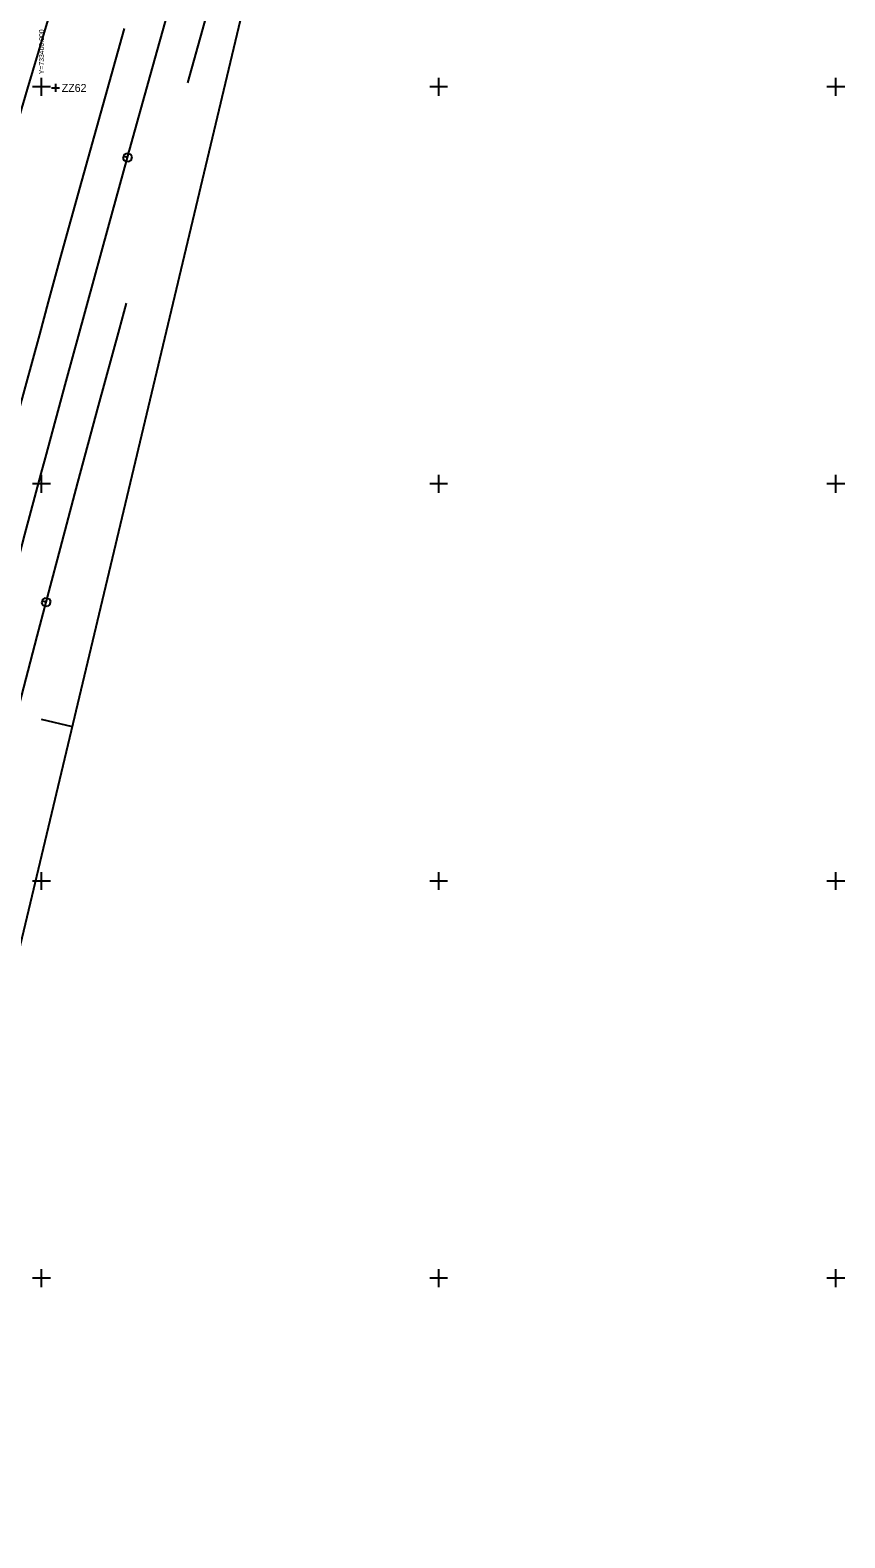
# Model space of a CAD drawing. Extents: x -733601 to -733291, y -1137892 to -1137187.
# Drawn here: x -733401.4 to -733298.9, y -1137682.7 to -1137492.9 of the extents above; entities that cross this region are included whole.
import ezdxf

# ---------------------------------------------------------------- set-up
doc = ezdxf.new("R2010")
doc.units = 0
for name, color, linetype in [('BP_ZBP_a_ZZ', 7, 'Continuous'), ('Krizky_Hektom_sit', 7, 'Continuous'), ('Rozvrzeni', 7, 'Continuous'), ('SIT_PUV_ZELEZNICE', 7, 'Continuous')]:
    doc.layers.add(name, color=color, linetype=linetype)

msp = doc.modelspace()

# ---------------------------------------------------------------- linework, layer by layer
at = {"layer": 'BP_ZBP_a_ZZ'}
for p, q in [((-733398.74, -1137500.13), (-733397.74, -1137500.13)), ((-733398.24, -1137499.63), (-733398.24, -1137500.63))]:
    msp.add_line(p, q, dxfattribs=at)
at = {"layer": 'Krizky_Hektom_sit'}
for p, q in [((-733400, -1137501.13), (-733400, -1137498.87)), ((-733350, -1137501.13), (-733350, -1137498.87)), ((-733300, -1137501.13), (-733300, -1137498.87)), ((-733398.87, -1137500), (-733401.13, -1137500)), ((-733348.87, -1137500), (-733351.13, -1137500)), ((-733298.87, -1137500), (-733301.13, -1137500)), ((-733398.87, -1137550), (-733401.13, -1137550)), ((-733400, -1137551.13), (-733400, -1137548.87)), ((-733348.87, -1137550), (-733351.13, -1137550)), ((-733350, -1137551.13), (-733350, -1137548.87)), ((-733298.87, -1137550), (-733301.13, -1137550)), ((-733300, -1137551.13), (-733300, -1137548.87)), ((-733400, -1137601.13), (-733400, -1137598.87)), ((-733350, -1137601.13), (-733350, -1137598.87)), ((-733300, -1137601.13), (-733300, -1137598.87)), ((-733398.87, -1137600), (-733401.13, -1137600)), ((-733348.87, -1137600), (-733351.13, -1137600)), ((-733298.87, -1137600), (-733301.13, -1137600)), ((-733400, -1137651.13), (-733400, -1137648.87)), ((-733350, -1137651.13), (-733350, -1137648.87)), ((-733300, -1137651.13), (-733300, -1137648.87)), ((-733398.87, -1137650), (-733401.13, -1137650)), ((-733348.87, -1137650), (-733351.13, -1137650)), ((-733298.87, -1137650), (-733301.13, -1137650))]:
    msp.add_line(p, q, dxfattribs=at)
at = {"layer": 'Rozvrzeni'}
msp.add_line((-733400.05, -1137579.62), (-733396.16, -1137580.55), dxfattribs=at)
msp.add_lwpolyline([(-733564.93, -1137648.32), (-733492.01, -1137341.87), (-733347.54, -1137376.25), (-733420.47, -1137682.7)], close=True, dxfattribs=at)
at = {"layer": 'SIT_PUV_ZELEZNICE'}
for p, q in [((-733389.72, -1137509.02), (-733389.65, -1137508.78)), ((-733389.65, -1137508.78), (-733389.58, -1137508.54)), ((-733389.17, -1137508.91), (-733389.65, -1137508.78)), ((-733389.58, -1137508.54), (-733389.27, -1137508.36)), ((-733389.27, -1137508.36), (-733388.79, -1137508.5)), ((-733388.79, -1137508.5), (-733388.62, -1137508.81)), ((-733388.62, -1137508.81), (-733388.75, -1137509.29)), ((-733389.54, -1137509.33), (-733389.72, -1137509.02)), ((-733389.06, -1137509.46), (-733389.54, -1137509.33)), ((-733388.75, -1137509.29), (-733389.06, -1137509.46)), ((-733399.96, -1137564.99), (-733399.89, -1137564.75)), ((-733399.78, -1137565.3), (-733399.96, -1137564.99)), ((-733399.89, -1137564.75), (-733399.83, -1137564.51)), ((-733399.41, -1137564.88), (-733399.89, -1137564.75)), ((-733399.83, -1137564.51), (-733399.52, -1137564.33)), ((-733399.3, -1137565.43), (-733399.78, -1137565.3)), ((-733399.52, -1137564.33), (-733399.04, -1137564.46)), ((-733398.99, -1137565.25), (-733399.3, -1137565.43)), ((-733399.04, -1137564.46), (-733398.86, -1137564.77)), ((-733398.86, -1137564.77), (-733398.99, -1137565.25))]:
    msp.add_line(p, q, dxfattribs=at)
for points in [[(-733381.59, -1137499.49), (-733379.48, -1137492), (-733376.74, -1137482.38), (-733373.97, -1137472.77), (-733371.18, -1137463.17), (-733369.48, -1137457.37)], [(-733408.19, -1137579.63), (-733407.17, -1137575.72), (-733404.63, -1137566.05), (-733404, -1137563.67), (-733402.08, -1137556.38), (-733400.03, -1137548.69), (-733399.5, -1137546.72), (-733396.9, -1137537.06), (-733394.52, -1137528.33), (-733394.27, -1137527.41), (-733391.62, -1137517.77), (-733389.17, -1137508.91), (-733388.95, -1137508.13), (-733388.91, -1137507.99), (-733386.27, -1137498.5), (-733383.85, -1137489.82)], [(-733424.81, -1137581.74), (-733423.59, -1137577.27), (-733420.95, -1137567.63), (-733420.17, -1137564.8), (-733418.28, -1137557.99), (-733415.58, -1137548.36), (-733412.86, -1137538.74), (-733410.12, -1137529.12), (-733408.74, -1137524.3), (-733407.35, -1137519.51), (-733404.56, -1137509.91), (-733401.75, -1137500.31), (-733398.91, -1137490.72)], [(-733412.78, -1137578.38), (-733410.54, -1137569.84), (-733410.01, -1137567.82), (-733410.01, -1137567.81), (-733408, -1137560.17), (-733405.43, -1137550.5), (-733403.16, -1137542.02), (-733402.84, -1137540.85), (-733400.23, -1137531.19), (-733399.1, -1137527.07), (-733397.59, -1137521.55), (-733394.93, -1137511.91), (-733392.24, -1137502.27), (-733389.54, -1137492.65)], [(-733403.08, -1137578.85), (-733400.54, -1137569.18), (-733399.41, -1137564.88), (-733397.99, -1137559.51), (-733395.42, -1137549.84), (-733392.82, -1137540.19), (-733390.2, -1137530.54), (-733389.3, -1137527.24)]]:
    msp.add_lwpolyline(points, dxfattribs=at)

# ---------------------------------------------------------------- texts
at = {"layer": 'BP_ZBP_a_ZZ'}
msp.add_text('ZZ62', height=1, dxfattribs=at).set_placement((-733397.46, -1137500.65))
at = {"layer": 'Krizky_Hektom_sit'}
msp.add_text('Y=733400.000', height=0.625, rotation=90, dxfattribs=at).set_placement((-733399.69, -1137498.42))

doc.saveas('drawing.dxf')
